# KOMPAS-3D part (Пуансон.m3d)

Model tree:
1. Копирование:2  (with: Операция вращения:1, Скругление:1, Скругление:2)  (labels: Копия тела : Тело 1; Копия грани : Копия тела : Тело 1; Копия грани : Операция вращения:1; Копия грани : Скругление:1)
2. Эскиз:1
3. Операция вращения:1
     Угол 1 = 360

Referenced files in C:\Users\andrey\Desktop\Заказ 1793547 (Черч)\Дет. 85\: Заготовка дет. 85.m3d
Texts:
  Копия тела : Тело 1
  Копия грани : Копия тела : Тело 1
  Копия грани : Операция вращения:1
  Копия грани : Скругление:1
  Копия поверхности : Скругление:1
  Копия грани : Скругление:2
  Копия поверхности : Скругление:2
